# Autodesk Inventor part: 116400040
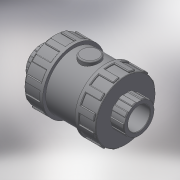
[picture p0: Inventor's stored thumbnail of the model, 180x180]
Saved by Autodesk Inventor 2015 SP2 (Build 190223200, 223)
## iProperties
Created: 2017-11
Part Number: 116400040
Material: Generic
Description: PLASSON FOOT VALVE CEM PVC 40
Document SubType Name: Modeling
Designer: KIM
Density: 1 g/cm^3
Appearance: Default
Author: KIM
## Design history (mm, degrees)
derived "116400 - 116000.ipt"
feature "Solid1::116400 - 116000.ipt"
tag "TaggingFeature1"
body "Solid1"
other parameters: "d3" = 26, "d4" = 32, "d5" = 18.2, "d7" = 56, "d8" = 72, "d13" = 1.2, "d23" = 26, "d24" = 76.8, "d25" = 0.8, "d26" = 1.2, "d27" = 12, "d28" = 6, "d29" = 19.5, "d30" = 0, "d35" = 1.2, "d45" = 360 deg, "d47" = 0.8, "d51" = 24, "d53" = 0, "d54" = 1.6, "d56" = 8, "d57" = 4, "d59" = 0, "d60" = 1.2, "d62" = 360 deg, "l_" = 26
